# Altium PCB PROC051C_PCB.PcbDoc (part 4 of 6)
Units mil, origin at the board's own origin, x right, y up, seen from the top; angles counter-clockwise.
Board outline 3304.03 x 2647.77 mil, 6 copper layers (TOP, L2, L3, L4, L5, BOTTOM), stack 55.54 mil thick; 370 components, 273 nets, 1273 pads, 1381 vias.
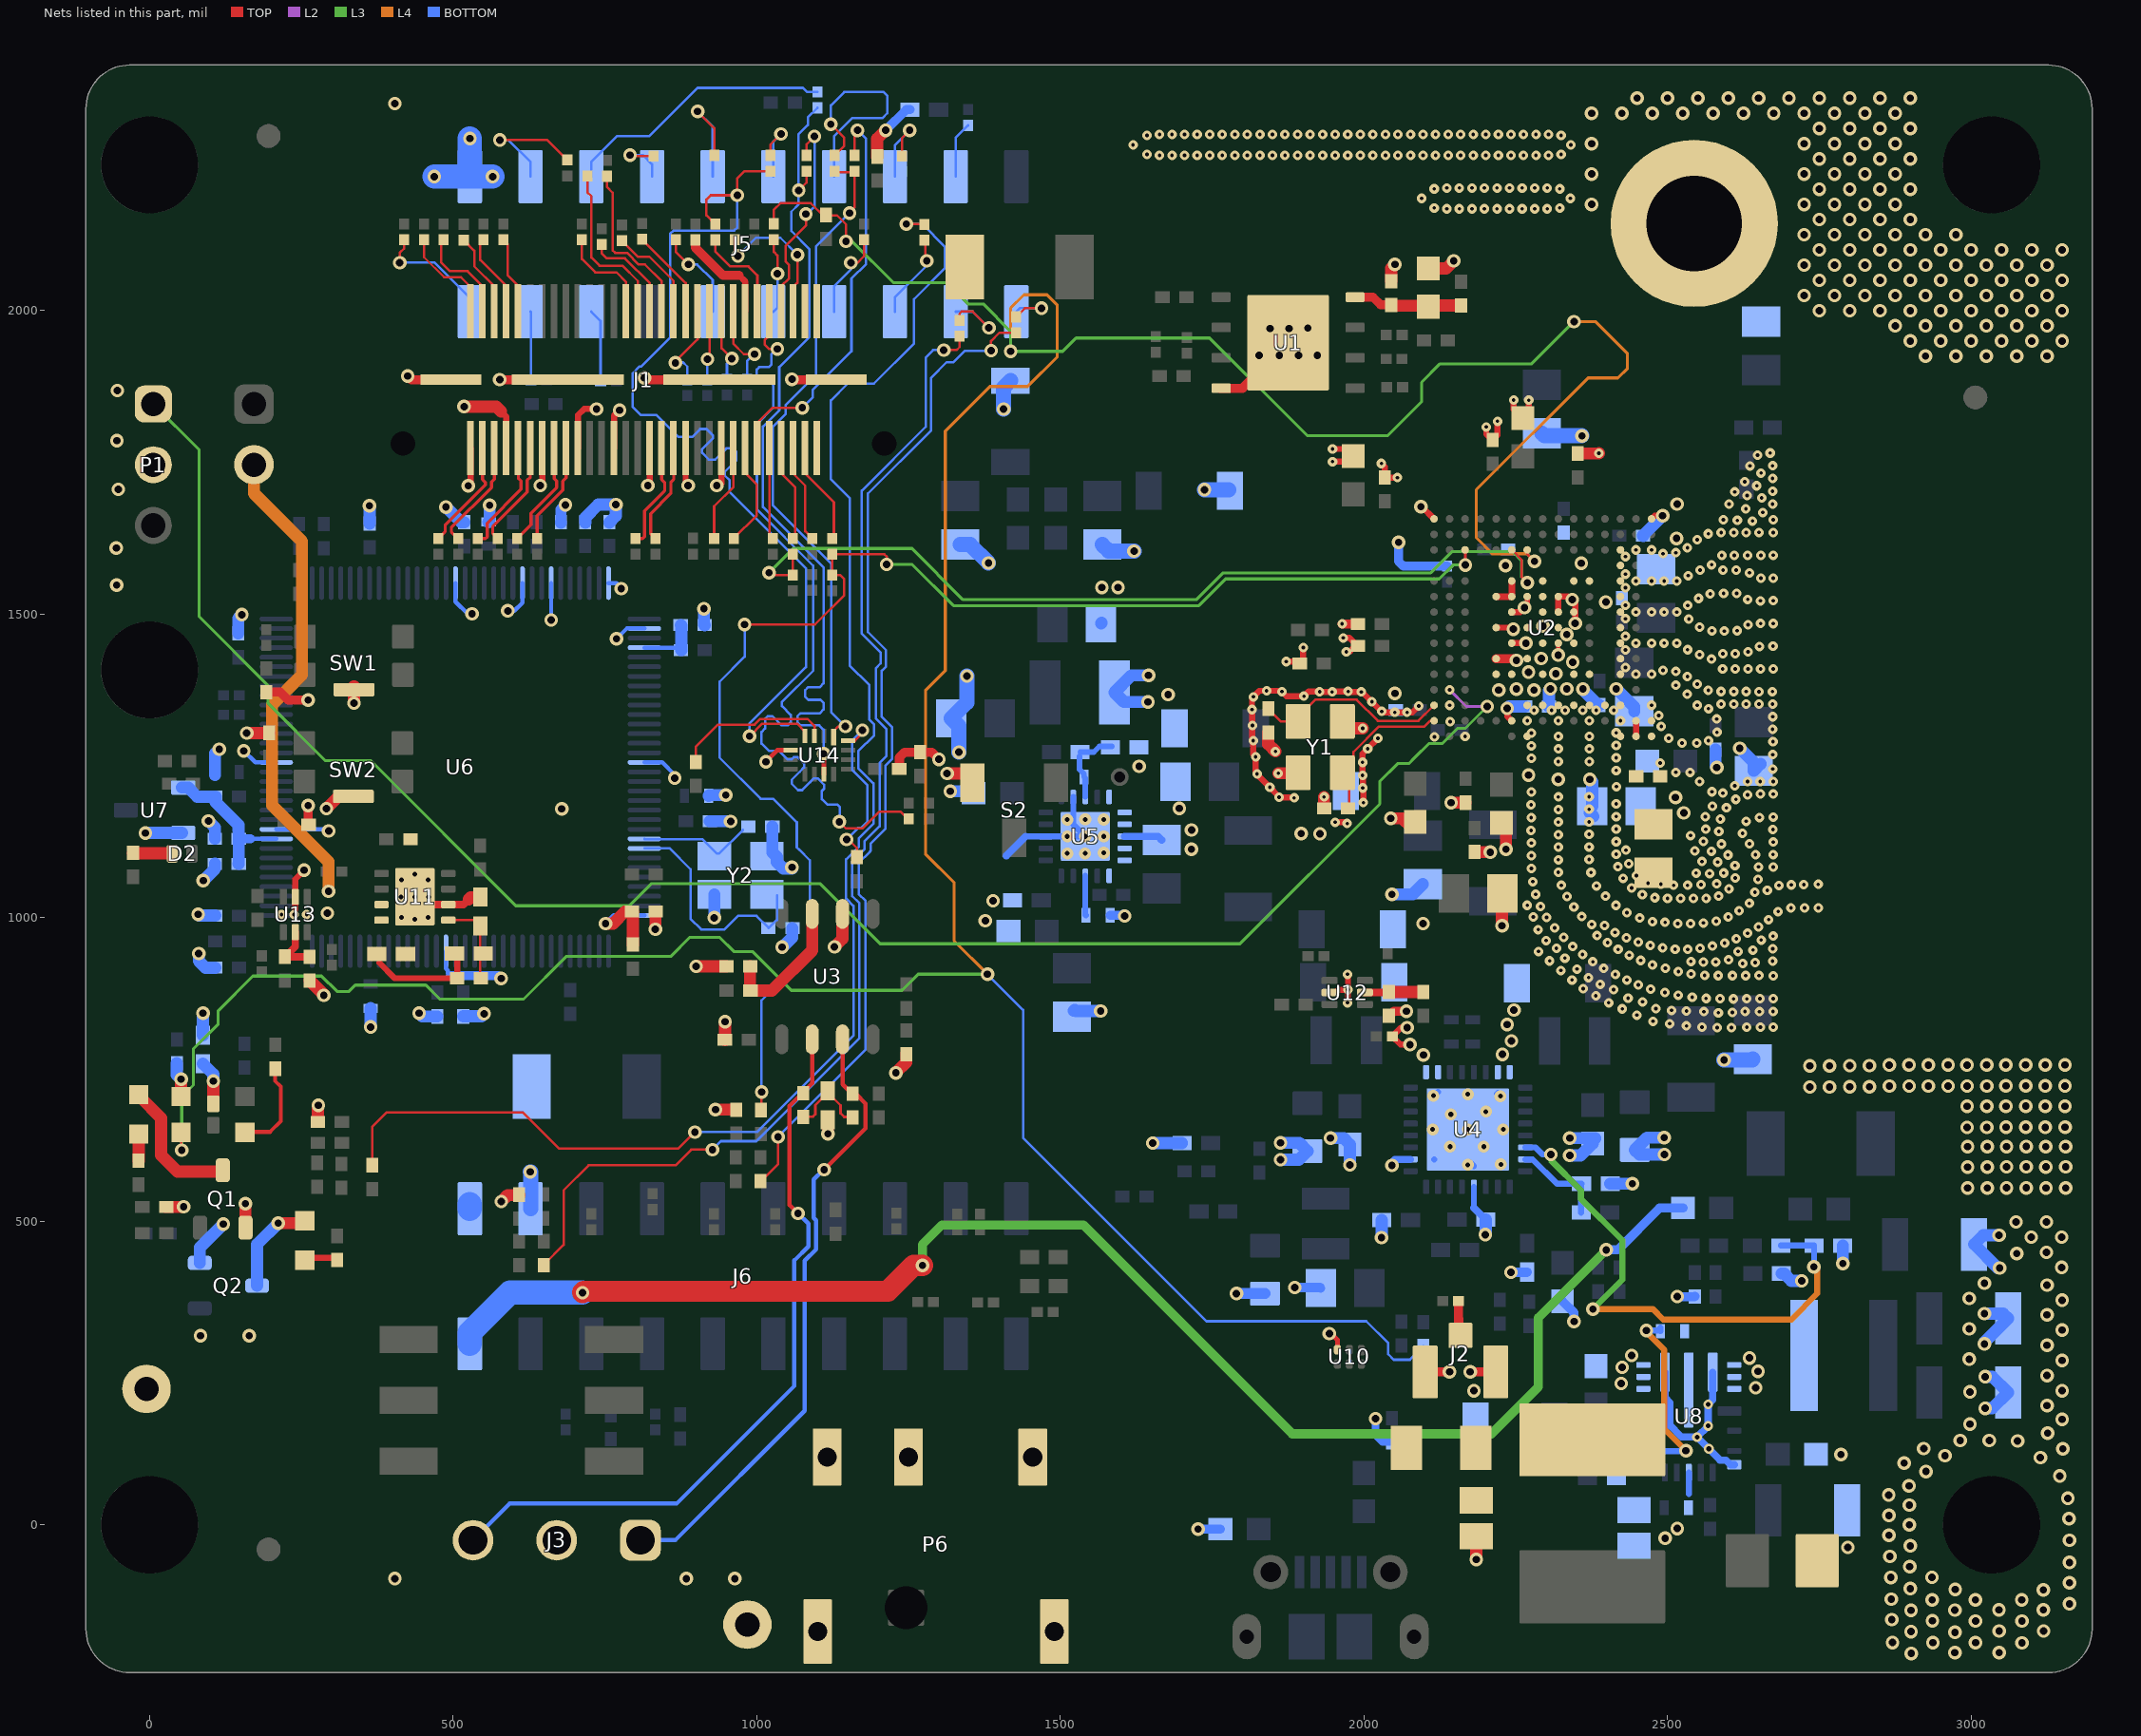
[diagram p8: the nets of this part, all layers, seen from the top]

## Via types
v1: diameter 22.4, hole 12.2, TOP to BOTTOM, tented both sides, 810 vias
v2: diameter 13.77/15.74 (per signal layer), hole 5.9, TOP to L2, tented both sides, 528 vias
v3: diameter 19.68, hole 7.87, TOP to BOTTOM, 23 vias
v4: diameter 19.68, hole 7.87, TOP to BOTTOM, tented both sides, 7 vias
v5: diameter 22.4, hole 12.1, TOP to BOTTOM, tented both sides, 7 vias
v6: diameter 16, hole 8, TOP to BOTTOM, tented both sides, 4 vias
v7: diameter 13.77/15.74 (per signal layer), hole 5.9, TOP to L2, tented top, 1 vias
v8: diameter 22.4/22.4/22.4/22.4/22.4/22.4 (per signal layer), hole 12.2, TOP to BOTTOM, tented both sides, 1 vias

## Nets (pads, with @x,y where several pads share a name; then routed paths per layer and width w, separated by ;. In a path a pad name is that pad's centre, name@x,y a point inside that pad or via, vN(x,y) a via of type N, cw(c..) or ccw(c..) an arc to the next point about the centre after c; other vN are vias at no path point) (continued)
AR_TDO_SOP0: R67.2 R71.1 R89.1 U2.N13 | length 2331.7
  TOP w4: v1(980,1483) 980.2,1482.8 1025.12,1482.8 1025.32,1483 1096,1483 1144,1531 1144,1558 1137.29,1564.71 R71.1@1124.33,1564.71 1124.25,1564.79 R67.2@1124.25,1598.73 1210.27,1598.73 1214,1595 v1(1214,1582) ; R89.1@1006.58,682.45 R89.1@1006.58,683.24 1008,684.66 v1(1008,713) ; U2.N13@2166.6,1605.85 2167,1606.25 2167,1605.85 v1(2167,1581)
  L3 w5: v1(1214,1582) 1256,1582 1324,1514 1728.14,1514 1772.14,1558 2124,1558 2147,1581 v1(2167,1581)
  BOTTOM w4: v1(980,1483) 980,1430 938.8,1388.8 938.8,1263.62 1006.42,1196 1027.14,1196 1066,1157.14 1066,1115.86 1069.66,1112.2 1070.09,1112.2 1087.5,1094.8 1087.5,943.5 1008,864 v1(1008,713)
AR_TMS: R65.2 R69.1 U2.N10 | length 1508.7
  TOP w4: v1(1020.36,1568.35) 1024,1564.71 R69.1@1059.25,1564.71 R65.2@1059.25,1598.73 ; U2.N10@2243.37,1605.85 2260,1589.22 2260,1561 v1(2269,1552)
  L3 w5: v1(1020.36,1568.35) 1060.11,1608.1 1255.7,1608.1 1339.8,1524 1724,1524 1768,1568 2110,1568 2145.3,1603.3 2244.56,1603.3 2259.7,1588.16 2259.7,1561.3 v1(2269,1552)
AR_VBGAP: C56.2 U2.B10 | length 54.1
  TOP w10: v1(2236,1345) 2236,1331.73 U2.B10@2243.37,1324.36
  BOTTOM w20: v1(2236,1345) 2239,1348 C56.2@2265.16,1348
AR_VOUT_PA: C10.2 C65.2 C83.2 R137.2 U2.A2 U2.B2 | length 25.6
  TOP w10: U2.A2@2448.09,1298.77 U2.B2@2448.09,1324.36
  other v1: 2526.79,1172.71 2513.12,1198
AR_VSENSE: P1.1 U2.D14 | length 3030.7
  L2 w5: v2(2141.01,1375.54) 2168.54,1348 v1(2203,1348)
  L3 w5: P1.1@6.27,1846.15 81.5,1770.92 81.5,1496 195.2,1382.3 195.2,1352.8 289,1259 364,1259 603.2,1019.8 790.3,1019.8 826.7,1056.2 1104,1056.2 1203.2,957 1795.63,957 2026.09,1187.46 2026.09,1224.71 2055.28,1253.9 2073.86,1253.9 2083.8,1263.84 2083.9,1263.84 2106.8,1286.74 2107.88,1286.74 2107.92,1286.78 2128.7,1286.78 2153.92,1312 2167,1312 v1(2203,1348)
AR_WARMRST: DS2.2 R15.1 R18.1 R149.2 U2.N9 | length 6596.4
  TOP w4: DS2.2@52,647.46 DS2.2@52,646.47 52,618 v1(53,617) ; R18.1@1028.21,2143.06 1028.21,2166.22 1038.99,2177 1089.07,2177 1111.26,2154.8 R15.1@1114,2157.53 1114,2156.75 1132.24,2156.75 1147,2141.99 v1(1147,2114) ; U2.N9@2268.96,1605.85 2268.96,1599.04 v1(2281,1587)
  L3 w5: v1(53,617) 53,705.23 72.16,724.39 72.16,784.16 113,825 113,847 170,904 283.26,904 308.65,878.61 328.4,878.61 338.79,889 455,889 478,866 616,866 686.22,936.22 858.1,936.22 889.58,967.7 938.89,967.7 962.29,944.3 992.7,944.3 1056.7,880.3 1239.3,880.3 1266,907 v1(1380,907) ; v1(1147,2114) 1157,2114 1225,2046 1313,2046 1348,2011 1373,2011 1418,1966 v1(1418,1933) 1504,1933 1526,1955 1745.9,1955 1906.9,1794 2039,1794 2095,1850 2095,1881.86 2125.44,1912.3 2276.3,1912.3 v1(2346,1982)
  L4 w5: v1(1380,907) 1325,962 1325,1058 1277.98,1105.02 1277.98,1374.51 1310.48,1407.01 1310.48,1801.63 1383.88,1875.03 1446.03,1875.03 1495,1924 1495,2009 1478,2026 1440,2026 1418,2004 v1(1418,1933) ; v1(2281,1587) 2268.3,1599.7 2211.3,1599.7 2185,1626 2185,1705 2369,1889 2418.26,1889 2434.06,1904.81 2434.06,1929.34 2381.7,1981.7 2346,1981.7 2341.7,1981.7 2342,1982 v1(2346,1982)
  BOTTOM w4: v1(1380,907) 1438.7,848.3 1438.7,637.3 1740.61,335.39 2003.85,335.39 2040,299.23 2040,281 2049,272 2075.69,272 R149.2@2098,294.31
AR_XTALM: C9.2 U2.C15 Y1.1 | length 326.1
  TOP w4: C9.2@1842.36,1344.03 1862.93,1323.46 1891.58,1323.46 1892.3,1323.46 1892.3,1331.6 1919.8,1359.1 1987.9,1359.1 2022.68,1324.32 2089.79,1324.32 U2.C15@2115.42,1349.95
AR_XTALP: C15.2 U2.B15 Y1.3 | length 258.4
  TOP w4: C15.2@1975.7,1180.4 1975.53,1180.57 1975.53,1228.43 1965.14,1238.82 1982.7,1256.38 1982.7,1273.22 2024.48,1315 2099.67,1315 2109.03,1324.36 U2.B15@2115.42,1324.36
CAN_RX: R12.1 U14.3 | length 260.6
  TOP w4: R12.1@900,1256.68 900,1282 936.05,1318.05 996.31,1318.05 1005.76,1327.5 1083.63,1327.5 1095.13,1316 U14.3@1095.13,1299.5
CAN_TX: R11.1 U14.16 | length 286.9
  TOP w4: v1(1148,1129) 1151,1129 1165,1115 R11.1@1165,1099.68 ; U14.16@1150.24,1291.62 1161.62,1291.62 1174,1304 v1(1174,1309)
  BOTTOM w4: v1(1148,1129) 1166.8,1147.8 1171.8,1147.8 1182.54,1158.54 1182.54,1218.04 1157,1243.58 1157,1292 v1(1174,1309)
CS1: R1.2 R17.1 U14.11 | length 1358.5
  TOP w4: v1(1069,2198) 1082,2211 R17.1@1082,2229.73
  TOP w8: v1(1110,1270) 1110.87,1269.13 U14.11@1110.87,1236.5
  BOTTOM w4: R1.2@1100,2334.01 1084.08,2318.08 1084.08,2305.8 1069,2290.72 v1(1069,2198) 1069,2175 1057,2163 1057,2131 1087,2101 1087,1957 1037,1907 1037,1835.7 1010.3,1809.01 1010.3,1676.7 1110,1577 1110,1386 1104,1380 1085,1380 1080,1375 1080,1364 1085,1359 1105,1359 1110,1354 1110,1343 1104,1337 1072,1337 1067,1332 1067,1322 1072,1317 1103,1317 1110,1310 v1(1110,1270)
D_LOGGER: J5.4 R60.1 | length 214.1
  TOP w4: v1(577,2281) 654.99,2281 R60.1@688,2247.99
  BOTTOM w4: v1(577,2281) 591,2281 627.5,2244.5 J5.4@627.5,2220.72
GND: C1.1 C2.1 C3.1 C4.1 C5.1 C6.1 C7.1 C8.2 C9.1 C10.1 C11.1 C12.1 C13.1 C14.1 C15.1 C16.1 C17.1 C19.2 C20.1 C21.2 C22.2 C23.2 C24.1 C25.2 C26.2 C27.2 C28.2 C29.2 C30.2 C31.2 C32.2 C33.1 C34.2 C35.2 C36.1 C37.2 C38.2 C39.1 C40.2 C41.2 C42.1 C43.1 C44.2 C45.1 C46.2 C47.1 C48.1 C49.1 C50.1 C51.1 C52.1 C53.1 C54.1 C55.2 C56.1 C57.1 C58.1 C59.2 C60.2 C61.2 C62.2 C63.2 C64.1 C65.1 C66.1 C67.1 C68.2 C69.1 C70.2 C71.1 C73.2 C74.1 C75.1 C76.2 C77.2 C78.2 C79.2 C80.2 C81.2 C82.2 C83.1 C84.1 C85.2 C86.1 C87.1 C89.1 C90.1 C91.1 C92.1 C93.2 C94.1 C95.2 C96.2 C97.1 C98.2 C99.2 C100.2 C101.2 C102.2 C103.2 C104.2 C105.2 J1.18 J1.24 J1.30 J1.36 J1.42 J1.48 J1.54 J1.60 J1.MP1 J1.MP2 J1.MP3 J1.MP4 J2.2 J2.3 J3.2 J5.2 J6.4 P1.2 P6.2 P6.3 P6.4 P6.5 pad.1 Q1.2 Q2.2 R13.1 R73.1 R79.1 R83.1 R86.2 R88.1 R96.1 R110.1 R114.1 R118.1 R123.2 R125.1 R126.2 R138.1 R139.1 R145.1 R147.2 R153.1 R158.2 R167.1 R174.1 R175.1 R190.1 R193.1 R208.2 S2.3 SW1.5 SW2.5 TP1.1 TP3.1 U1.4 U1.9 U2.A1 U2.A3 U2.A5 U2.A7 U2.A9 U2.A13 U2.A15 U2.B1 U2.B3 U2.B5 U2.B7 U2.B9 U2.B14 U2.C1 U2.C3 U2.C4 U2.C5 U2.C6 U2.C7 U2.C8 U2.C9 U2.C14 U2.E1 U2.E2 U2.E3 U2.E5 U2.E6 U2.E8 U2.E10 U2.E11 U2.F3 U2.F9 U2.F11 U2.G1 U2.G2 U2.G3 U2.G6 U2.G7 U2.G8 U2.G10 U2.H3 U2.H7 U2.H9 U2.H11 U2.J1 U2.J2 U2.J3 U2.J6 U2.J7 U2.J8 U2.J10 U2.K3 U2.K7 U2.K8 U2.K9 U2.K10 U2.K11 U2.L1 U2.L2 U2.L3 U2.L5 U2.L6 U2.L8 U2.L10 U2.M3 U2.N1 U2.N2 U2.N3 U2.R1 U2.R15 U3.2 U4.4 U4.10 U4.17 U4.18 U4.23 U4.24 U4.33 U5.2 U5.5 U5.6 U5.7 U5.8 U5.9 U5.10 U5.11 U5.18 U5.21 U6.10 U6.17 U6.48 U6.55 U6.58 U6.64 U6.66 U6.80 U6.114 U7.2 U8.3 U8.5 U8.6 U8.7 U8.8 U8.10 U8.11 U8.12 U8.13 U8.17 U8.20 U10.3 U11.6 U11.9@436.9,1034.5 U12.2 U13.2 U14.6 Y1.2 Y1.4 Y2.2 Y2.4 | length 9431.9
  TOP w7: U2.J7@2318.89,1503.49 U2.J7@2320.14,1503.49 U2.J7@2320.61,1503.49 ; v1@2320.14,1432.71 U2.G7@2320.14,1452.31
  TOP w7.5: v1(1015,1257) 1033.87,1275.87 U14.6@1055.76,1275.87
  TOP w8: v1(1943,315) 1943,318 1956.32,304.68 U10.3@1956.32,288.57
  TOP w9: v1@2268.96,1515.31 U2.K9@2268.96,1529.08
  TOP w10: v2@240,1013 240,1063.8 v1(254.6,1078.4) ; v1(524.98,1711.53) 528.62,1715.17 J1.60@528.62,1773.27 ; 579,1834 587.67,1825.33 J1.54@587.67,1773.27 ; v1(643.53,1711.97) 646.73,1715.17 J1.48@646.73,1773.27 ; J1.42@705.78,1773.27 705.78,1828 715.78,1838 v1(736,1838) ; J1.36@764.84,1773.27 764.84,1826.84 v1(774,1836) ; v1(820.61,1711.89) 823.89,1715.17 J1.30@823.89,1773.27 ; J1.24@882.95,1773.27 882.95,1716.05 v1(887,1712) ; v1(934,1712) 938.83,1712 942,1715.17 J1.18@942,1773.27 ; v2(1872,1422) 1895.7,1422 1900,1426.3 v2(1900,1445) ; v2(1885,1197.5) 1885,1198.4 v2(1860.1,1198.4) 1860.1,1199.9 v2(1845,1215) 1824,1236 v2(1824,1237) 1821.6,1239.4 v2(1821.6,1265) 1817.7,1268.9 v2(1817.7,1291.5) 1816.3,1292.9 v2(1816.3,1316.6) 1816.3,1342.3 v2(1815.7,1342.9) 1815.7,1361.7 v2(1818,1364) 1827.9,1373.9 v2(1839.7,1373.9) 1863.6,1373.9 v2(1865,1372.5) 1872.6,1364.9 v2(1901.3,1364.9) 1908.8,1372.4 v2(1927,1372.4) 1927.4,1372 v2(1947.6,1372) 1948.43,1372.83 v2(1974.02,1372.83) 1974.95,1371.9 1995.7,1371.9 v2(1995.8,1372) 1997,1372 2030.65,1338.35 v2(2050.83,1338.35) v2(2071,1338.35) 2079.79,1338.35 v2(2090.24,1348.8) ; U12.2@1943.37,876.9 1953.7,876.9 1958.3,881.5 v2(1973.69,881.5) ; v2(1948.3,1751.3) 1973,1751.3 C89.1@1982.1,1760.4 1970.4,1772.1 v2(1948.3,1772.1) ; v2(1952.62,1157.3) 1970.3,1157.3 v2(1972.4,1155.2) ; v2(1966,1461) 1976,1461 1989.66,1447.34 1986.31,1444 1982,1444 1976,1438 v2(1971,1438) ; v2(1973,859.98) 1973.69,860.66 v2(1973.69,881.5) ; v2(1973,907) 1973.69,906.31 v2(1973.69,881.5) ; v2(1999.1,1189.7) 1999.1,1212.8 v2(1998.1,1213.8) 1998.1,1234 v2(1997.7,1234.4) v2(1997.7,1256.1) 1997.7,1270 v2(2006.2,1278.5) v2(2023.15,1295.45) ; v2(2028.8,1748.3) 2034.5,1742.6 C6.1@2034.5,1725.28 2034.5,1724.9 v2(2055.3,1724.9) ; v1(2071,819) 2060.99,819 R167.1@2046.59,804.6 2060.19,791 v1(2076,791) ; v1(2094,1677) 2095.45,1677 U2.R15@2115.42,1657.03 ; v2(2201.4,1808.4) 2201.4,1796.9 2211.4,1786.9 2211.95,1786.9 2219.9,1794.85 v2(2219.9,1817.8) ; U2.H11@2217.78,1477.9 2248.55,1477.9 v1(2246,1475.35) v1@2246,1472 ; U2.G10@2243.37,1452.31 v1@2266.94,1452.31 ; U2.J10@2243.37,1503.49 2257.14,1503.49 v1(2264.45,1510.8) ; v2(2246.6,1852.7) 2246.6,1837.55 2261.25,1822.9 C87.1@2261.8,1822.9 2271.5,1832.6 v2(2271.5,1852.5) ; U2.J7@2320.14,1503.49 U2.K7@2320.14,1529.08 2336.12,1529.08 2348,1517.2 v1(2348,1485) ; U2.R1@2473.68,1657.03 2478.69,1662.04 v1(2491.96,1662.04)
  TOP w11: U2.K11@2217.78,1529.08 U2.K10@2243.37,1529.08 U2.L10@2243.37,1554.67
  TOP w12: v4(436.9,1034.5) 449.7,1021.7 516.9,1021.7 525.7,1030.5
  TOP w15: R73.1@192.05,1372.02 214.98,1372.02 228.5,1358.5 v1(261,1358.5) ; R79.1@261.15,1153.14 v1(261.15,1185) ; v1(425.2,1892.3) 431.24,1886.26 J1.MP4@496.12,1886.26 J1.MP4@496.73,1886.26 ; v1(576.76,1886.26) J1.MP3@688.64,1886.26 J1.MP3@689.25,1886.26 ; v1(815,1889) 817.74,1886.26 J1.MP2@938.64,1886.26 J1.MP2@939.25,1886.26 ; v1(1058,1887) 1058.74,1886.26 J1.MP1@1131.16,1886.26 J1.MP1@1131.77,1886.26 ; C97.1@1234.68,1245 1235,1245.32 1235,1264 1243.69,1272.69 R208.2@1269,1272.69 1288.31,1272.69 v1(1300,1261) ; U1.4@1762.93,1872.18 U1.4@1764.89,1872.18 1800.13,1872.18 U1.9@1875.13,1947.18 ; v2(1964,1484) C4.1@1990.32,1484 ; C91.1@2041,838.32 2041.32,838 2049.32,846 v1(2070,846) ; J2.2@2100.93,252 v1(2141,252) ; v1(2175,252) J2.3@2217.07,252 ; U2.F11@2217.78,1426.72 2248.28,1426.72 v1(2251,1424)
  TOP w20: R110.1@26.62,523.77 R110.1@27.4,523.77 v1@55,523.77 ; Q1.2@157.98,489.51 v1(158,529) ; v1(160,1304.2) C11.1@197.3,1304.2 ; C92.1@263.6,896.9 287.1,873.4 v1(287.1,872.3) ; R114.1@277.32,664 277.32,690.32 v1(278,691) ; v1(291.2,1179.7) 311.4,1199.9 SW2.5@335.7,1199.9 ; v1(336.65,1353.5) SW1.5@336.65,1375.52 SW1.5@336.65,1381.42 ; v1(518,1842) 571,1842 579,1834 ; 525.7,1030.5 529.11,1033.91 R193.1@544.9,1033.91 ; v1(579.2,532.5) 589.85,543.15 R96.1@608.78,543.15 ; v1(833,981) 833.3,981.3 C71.1@833.3,1010.5 ; v1(900,920) C16.1@949.91,920 C16.1@950.3,920 ; v1(932,684) 964.87,684 R88.1@966.12,682.75 ; C20.1@947.89,798.85 v1(947.89,828.89) ; v1(1117.1,644.1) C24.1@1117.1,667.48 C24.1@1117.1,671.8 ; v1(1128,952) 1141.31,965.31 U3.2@1141.31,1006.33 U3.2@1141.31,1007.31 ; R13.1@1198.4,2252.95 R13.1@1198.4,2253.73 1198.4,2283 v1(1212.4,2297) ; v1(1229,744.5) 1246.3,761.8 R86.2@1246.3,775.01 R86.2@1246.3,775.8 ; v1(1313.43,1237.76) 1339.62,1237.76 S2.3@1355.1,1222.28 ; C9.1@1842.36,1305.43 C9.1@1842.36,1305.05 1842.36,1285.94 v2(1854.3,1274) ; v2(1859,1238) 1891.48,1238 Y1.2@1892.3,1238.82 ; C15.1@1934.32,1180.4 v2(1934.32,1198.99) ; Y1.4@1965.14,1323.46 1976.6,1312 v2(1998,1312) ; v1(2044.25,1163.62) 2063.4,1163.62 2076.78,1150.23 C14.1@2084.45,1157.9 ; C2.1@2044.9,2048.2 C2.1@2044.9,2048.59 2044.9,2069.9 v1(2051,2076) ; C1.1@2102,2068.5 C1.1@2104.5,2071 ; C1.1@2106,2069.5 2135.5,2069.5 v1(2148,2082) ; v1(2143.51,1189.51) C12.1@2167.2,1189.51 C12.1@2167.2,1189.9 ; C90.1@2184,1108.32 2207.68,1108.32 v1(2208,1108) ; v1(2185,-57) C79.2@2185,-18.53 C79.2@2187.47,-21 ; C17.1@2213.1,1028.1 C17.1@2213.1,1037.6 ; C13.1@2226.5,1156.4 2234,1148.9 v1(2234,1113) ; v1(2227.44,987) 2227.44,1039.44 C17.1@2228,1040 ; C3.1@2352,1764.68 2386.68,1764.68 v2(2387,1765)
  BOTTOM w7: v1(155,1275) 174.09,1255.91 U6.17@208.64,1255.91 ; U6.10@208.64,1145.68 292.32,1145.68 v1(295,1143) ; U6.114@488.17,944.89 488.17,916.23 491.4,913 491.5,913 491.5,908.5 495.2,904.8 ; U6.48@503.92,1551.19 503.92,1520.59 524.01,1500.5 v1(531,1500.5) ; v1(590,1505.5) 601,1505.5 614.15,1518.65 U6.55@614.15,1551.19 ; v1(661.4,1490.3) U6.58@661.4,1551.19 ; U6.64@755.88,1551.19 769,1551.19 777,1543.19 v1(777,1542) ; v1(769,1459.5) 785.89,1476.39 U6.66@814.94,1476.39 ; U6.80@814.94,1255.91 844.49,1255.91 865,1235.4 v1(865,1230)
  BOTTOM w10: C61.2@106.73,1233.92 106.53,1233.72 106.53,1233.62 106.73,1233.62 106.94,1233.42 108.35,1234.83 108.35,1235 C61.2@107.94,1235.41 ; 1443.04,1134.04 U5.18@1476.04,1134.04 ; U5.18@1476.08,1134 v3(1511.46,1134) v4(1541.04,1134) 1521.35,1153.69 U5.2@1521.35,1198.96 ; U4.33@2115.94,602.06 U4.33@2116,602 ; U4.33@2121,712 U4.33@2122.06,713.06 ; U4.33@2175,597 U4.33@2181.11,590.89 ; 2181.11,521.89 U4.4@2181.11,556.78 ; U4.33@2219,710 U4.33@2220.48,711.48 ; 2535,51 U8.20@2535,86.19
  BOTTOM w12: 1411,1102 1443.04,1134.04 ; U5.8@1606,1134 1661,1134 C59.2@1667,1128 ; v1(2019,175) 2019,148 2030.68,136.32 R174.1@2046,136.32 ; v1(2046,592) 2046,597 2051.06,602.06 U4.10@2076.78,602.06 ; 2181.11,521.89 2200,503 C22.2@2200.62,503 ; U8.3@2460.2,155.09 2493.09,155.09 2503.01,165.01 2523.01,145 v6@2548.23,145 ; U8.8@2495.63,251.54 2495.63,209.5 2504,201.13 2504,166 ; U8.10@2574.37,251.54 2574.37,206 v6(2567,198.63) v6(2567,163) v6(2548.62,144.62) v6(2568,125.23) 2586.53,106.7 2596.3,106.7 2604.02,98.98 U8.17@2609.8,98.98
  BOTTOM w15: 495.2,904.8 574.3,904.8 v1(579.1,900) ; v1(1212.4,2297) 1246.4,2331 R147.2@1252.38,2331 ; C73.2@1582,1004 v1@1605,1004 ; v1(1727,-7) R175.1@1763.5,-7 ; v1(1886,391) 1928,391 C93.2@1929,390 ; v1(2057.1,1618.38) 2057.1,1586.9 2065.01,1578.99 C8.2@2137,1578.99 ; v1(2242,416) 2267.38,416 2268,415.38 R158.2@2269,416.38 ; C94.1@2327,368.5 2346,349.5 v1(2346,335) ; v1@2516.32,376.32 v1(2516,376) 2544.68,376 R138.1@2545,376.32
  BOTTOM w18: R125.1@677.52,1651.53 677.52,1672.52 v1(685,1680) ; v1(1790,381) C81.2@1837,381
  BOTTOM w20: v1(-7,1139.5) -2,1139.5 -2,1139.69 U7.2@53.36,1139.69 ; v1(80,1005.5) 81.94,1003.56 C69.1@107.96,1003.56 C69.1@108.35,1003.56 ; v1(81,941) 81,929 92.26,917.74 R153.1@107.96,917.74 ; Q2.2@82.76,431.4 82.76,456.76 v1(121.4,495.4) ; R118.1@88,806.62 v1(88,843) ; v1(88.4,1061.1) 107.95,1080.65 C67.1@107.95,1088.8 ; v1(97,1159.5) 107.89,1148.61 C66.1@107.89,1130.1 ; C61.2@107.94,1235.41 107.94,1270.74 v1(114.7,1277.5) ; C50.1@145.95,1468 C50.1@145.95,1468.39 145.95,1493.15 v1(152,1499.2) ; v1(362,1678.5) 362.52,1677.98 C43.1@362.52,1649.53 C43.1@362.52,1649.15 ; v1(364,820) C76.2@364,851 ; v1(444,843) 449.54,837.47 C75.1@473.68,837.47 ; v1(488,1676.5) 513.35,1651.15 C42.1@518.22,1651.15 ; C74.1@516.6,837.85 546.85,837.85 v1(550.9,841.9) ; C41.2@558.3,1651.85 560,1653.55 v1(560,1679.5) ; R125.1@677.52,1650.75 R125.1@677.52,1651.53 ; R126.2@717.68,1651.05 R126.2@717.68,1651.84 717.68,1659.18 739,1680.5 v1(768,1680.5) 768,1661.77 R123.2@757.28,1651.05 ; v1(913,1509) 913,1482.93 C49.1@914.04,1481.9 ; C62.2@921,1201 922,1202 v1(949,1202) ; C64.1@922.68,1159 955.5,1159 956,1158.5 v1(957,1158.5) ; v1(930,1000) 930.15,1000.15 Y2.4@930.15,1038.54 ; C63.2@1025.69,1150 1025.68,1107.86 1033.27,1100.28 1033.27,1091.73 1043.67,1081.33 1058,1081.33 v1(1058,1083) ; v1(1041.8,951.5) 1041.8,950.8 1058.68,967.68 C70.2@1058.69,983 ; v1(1318.83,1208.21) 1354.4,1208.21 R83.1@1357.35,1205.26 ; C40.2@1522.19,846.92 1523.74,848.47 1525.9,846.31 v1(1566.29,846.31) ; C95.2@1567.13,1485 C95.2@1568,1485.87 ; v1@1605,1004 v1(1606,1003) ; v1(1644.42,1355.5) 1604.71,1355.5 C44.2@1589.09,1371.13 1617.13,1399.18 v1(1645.22,1399.18) ; v1(1652,629) R190.1@1700.38,629 ; C19.2@1777.56,1705 C19.2@1779.27,1703.29 ; v1(1862.59,601.49) 1892.86,601.49 C35.2@1907,615.63 1893.52,629.11 v1(1862.59,629.11) ; v1(1945,637) 1966.5,637 C36.1@1977,626.5 v1(1977,593) ; v1(2029,473) 2029.38,473.38 C82.2@2029.38,502 ; v1(2046,1038.54) 2080.21,1038.54 C104.2@2097.09,1055.42 ; v1(2200,478) 2200.62,478.62 C22.2@2200.62,503 ; C56.1@2304.53,1348 2304.53,1374.53 v1(2307,1377) ; v1(2339,608.45) 2356.81,608.45 C54.1@2376.63,628.27 ; v1(2339,637) 2380.5,637 C54.1@2381,636.5 ; v1(2360.75,1376.8) 2360.75,1375.55 2385.82,1350.47 C51.1@2387.91,1350.47 ; C65.1@2372,1173 C65.1@2378,1167 ; v1(2372,1228) 2376,1224 C65.1@2376,1183.57 ; C77.2@2405.62,562 v1(2442,562) ; v1(2415.62,1376.86) 2445.08,1347.41 C52.1@2445.08,1340.29 ; C39.1@2460,1628.68 C39.1@2459.68,1629 2459.68,1629.68 v1(2491.96,1662.04) v1(2491.96,1662.04) ; v1(2494.45,638) 2466.44,638 C46.2@2446.07,617.63 2453.7,610 v1(2494.97,610) ; C57.1@2579,1277 2579,1249.66 v1(2581.16,1247.5) ; v1(2619,1279) 2642,1256 C58.1@2642,1242 C58.1@2653.2,1253.2 ; R139.1@2687.62,414 2692,414 2704,402 v1(2721,402) ; v1(2788.62,430.38) C78.2@2788.62,460 ; v1(3022,298) 3022,301.04 C30.2@3060.96,340 3052.96,348 v1(3022,348) ; v1(3023,192) 3034.96,192 C29.2@3060.96,218 3034.96,244 v1(3023,244) ; v1(3046,477) 3019.96,477 C31.2@3004.96,462 3043.96,423 v1(3047,423)
  BOTTOM w25: v1(627,581.5) 627.5,581.5 J6.4@627.5,520.72 ; v1(1333,1272.69) 1333,1315.69 C96.2@1320.21,1328.48 1346.04,1354.31 v1(1346.04,1398) ; C103.2@1335.31,1614.61 1351.47,1614.61 v1(1381.63,1584.45) ; v1(1406.57,1838) 1406.57,1873.41 C37.2@1417.79,1884.62 ; C98.2@1569,1614.51 1579.53,1603.98 v1(1621.43,1603.98) ; v1(1737.53,1705) C19.2@1777.56,1705 ; C100.2@2293,1798 2297.3,1793.7 v1(2358.99,1793.7) ; v1(2592.98,765.92) 2639.3,765.92 C80.2@2640.38,767
  BOTTOM w40: v1(469,2220.72) J5.2@527.5,2220.72 ; v1(527.5,2283.5) J5.2@527.5,2220.72 ; v1(565,2220.72) J5.2@527.5,2220.72
  other v1: 2901.31,-211.79 2973.18,-210.54 3046.16,-210.54 2870.41,-193.77 2937.07,-194.14 3007.25,-194.14 3083.71,-194.24 2973.55,-177 2901.17,-175.74 3046.16,-174.68 3119.29,-174.68 2936.3,-157.9 3007.25,-158.28 3083.71,-158.39 2869.37,-155.97 2901.17,-140.65 2973.18,-140.5 3045.91,-139.97 3118.84,-139.97 3162,-130.02 2935.92,-123.56 3007,-123.56 3083.46,-123.67 2868.72,-122.32 3119.08,-107.06 2973.78,-106.37 2900,-105 3161.85,-95.39 404,-88.5 884,-88.5 964,-88.5 2867.68,-86.6 2935.56,-86.48 2898.88,-68.71 3162,-61.96 2866.11,-51.88 2796.87,-37 2900,-34.53 3162,-25.28 2496,-22 2864.72,-17.26 2516,-6 2898.33,0 3161.35,10.21 2864.72,15.51 2898.33,32.58 3159.31,43.72 2864.26,49.21 2897.74,64.31 3146,80.47 2925.65,87.98 2889.65,101.83 3114.04,110.95 2957,114 2785.6,115.82 3151.17,125.15 2921.96,125.83 3076.52,138.19 2982,139 3030,139 3126.05,151.01 2998,166 3150,173.81 3125,196.64 2998,219 2181.22,221 3150,221 2645,226 2423.67,232.91 3125,246 2649,253 2425.13,259.59 3150,271 2997,273 2635,275 2441,279 3125,296 84,311.5 164,311.5 3150,321 2997,323 3125,346 3150,370 2997,373 3125,395 3022,398 3149,424 3075,447 3124,449 3099,474 3149,474 3074,499 3124,499 56,524 2994.26,554.8 3026.78,554.86 3058.36,555.07 3090.89,555.13 3123.16,554.94 3155.68,555 2994.18,589.42 3026.7,589.48 3058.28,589.69 3090.81,589.75 3123.08,589.56 3155.6,589.62 2994.13,622.85 3026.66,622.91 3058.23,623.12 3090.76,623.18 3123.03,622.99 3155.55,623.05 2993.36,654.72 3025.88,654.78 3057.46,655 3089.99,655.05 3122.26,654.86 3154.78,654.92 2993.28,689.35 3025.8,689.41 3122.17,689.49 3057.38,689.62 3089.9,689.68 3154.7,689.55 2734.34,721.25 2766.87,721.31 2800.11,721.69 2832.63,721.74 2865.3,722.77 2897.82,722.83 2929.52,722.77 2962.04,722.83 2993.23,722.77 3025.76,722.83 3057.33,723.04 3089.86,723.1 3122.13,722.91 3154.65,722.97 2734.26,755.88 2766.79,755.94 2800.02,756.31 2832.55,756.37 2865.21,757.4 2897.74,757.45 2929.44,757.4 2961.96,757.45 2993.15,757.4 3025.67,757.45 3057.25,757.67 3089.78,757.73 3122.05,757.54 3154.57,757.6 2098,774 2228,775 2243,797 2236,824 2247,848 2097.46,990.5 1376.48,995.16 1389.27,1027.91 1716,1113 1927.6,1138.34 1896.53,1138.8 1716.13,1144.48 678.8,1179.5 1696,1180 2320,1228 1629.78,1249.49 1677.49,1367.63 2051,1369.53 2222,1375 2280,1375 2251,1376.8 2334,1377 2316,1402 2271.2,1404.5 2344,1421 2292,1427 2320.15,1432.7 2266.95,1452.3 2334,1466.51 2295.05,1480.4 2398.5,1519.98 2343,1524 1568.39,1544.14 1594.84,1544.14 -54.3,1547.9 2233,1580 2358,1584 -54.8,1609.1 2514.69,1624.81 2515.86,1681.5 -51.5,1705.6 -53.7,1785.9 -52.9,1868.3 2925,1925 2975,1925 3025,1925 3075,1925 3125,1925 2900,1950 2950,1950 3000,1950 3050,1950 3100,1950 3150,1950 2875,1975 2925,1975 2975,1975 3025,1975 3075,1975 3125,1975 2750,2000 2800,2000 2850,2000 2900,2000 2950,2000 3000,2000 3050,2000 3100,2000 3150,2000 2725,2025 2775,2025 2825,2025 2875,2025 2925,2025 2975,2025 3025,2025 3075,2025 3125,2025 2750,2050 2800,2050 2850,2050 2900,2050 2950,2050 3000,2050 3050,2050 3100,2050 3150,2050 2725,2075 2775,2075 2825,2075 2875,2075 2925,2075 2975,2075 3025,2075 3075,2075 3125,2075 2750,2100 2800,2100 2850,2100 2900,2100 2950,2100 3000,2100 3050,2100 3100,2100 3150,2100 2725,2125 2775,2125 2825,2125 2875,2125 2925,2125 2975,2125 2750,2150 2800,2150 2850,2150 2900,2150 2375,2175 2725,2175 2775,2175 2825,2175 2875,2175 2750,2200 2800,2200 2850,2200 2900,2200 2375,2225 2725,2225 2775,2225 2825,2225 2875,2225 2750,2250 2800,2250 2850,2250 2900,2250 2375,2275 2725,2275 2775,2275 2825,2275 2875,2275 2750,2300 2800,2300 2850,2300 2900,2300 2375,2325 2425,2325 2475,2325 2525,2325 2575,2325 2625,2325 2675,2325 2725,2325 2775,2325 2825,2325 2875,2325 404,2341 2450,2350 2500,2350 2550,2350 2600,2350 2650,2350 2700,2350 2750,2350 2800,2350 2850,2350 2900,2350
  other v2: 2581.79,819 2605.35,819 2556.6,820 2630.55,820 2653,820 2674.2,820 2531.2,821.87 2503.31,825.5 2476.25,829.44 2449.63,839.67 2583.7,843.5 2607,843.9 2560,845.4 2651.5,845.4 2531.2,846.2 2627.6,845.6 2673.8,845.6 2506.5,847.4 2425.52,849.9 2481,850.5 2403.07,859.98 2459,861.5 2608.6,866.4 2630.6,866.5 2563.5,867.1 2586.4,866.6 2652.2,866.6 2674.1,866.9 2435,867.5 2540.7,869 2381.92,871.42 2517.6,872.5 2495.5,876.9 2411,881.5 2472,882.5 2361.23,883 2389,890.5 2452,889.5 2342.66,897.5 2433,897.5 2370,901.5 2673.9,904.5 2561.2,905.1 2583.6,904.7 2607.1,904.7 2628.8,904.7 2650.8,904.8 2414,906.5 2538.7,907.4 2517.9,911.5 2324.3,913.17 2351,915.5 2395,916.5 2496.6,916.7 2475.1,922.5 2623.8,924.7 2644.4,926.2 2559,926.8 2579.6,927.3 2377,927.5 2538.4,928 2673,928.5 2305.8,929 2455.7,929.7 2600.4,930.7 2331,933.5 2436.9,938.3 2360,939.5 2616,944.5 2640.7,946.8 2418.6,947.8 2512.5,948.1 2533.1,947.9 2673.5,949.1 2317,949.5 2492,950.5 2553.7,949.6 2344,952.5 2574,953.3 2471.7,954.3 2594,958.3 2401.3,959.1 2451.8,959.9 2300,962.5 2654.2,963.3 2613.3,965.5 2432.4,967.1 2329,967.5 2384.1,970.5 2673.8,969.7 2631.9,974.5 2413.7,975.8 2287,980.5 2314,983.5 2649.7,984.9 2396.4,987.1 2375.1,989.1 2517,990.5 2538,990.5 2496,992.5 2559,991.5 2475,993.5 2580,994.5 2666.5,996.9 2301,1000.5 2454,999.5 2279,1001.5 2358.8,1001.8 2600,1001.5 217.33,1005.44 238,1005.44 258.67,1005.44 2433,1008.5 2682.2,1010.3 2618,1011.5 2703.3,1016.4 2725.8,1016.4 2748.6,1016.3 2291,1018.5 2345.8,1017.8 2269,1020.5 2415,1020.5 2634.7,1023.7 2500,1032 2521.5,1032 2542.5,1032 2563.5,1032 2479,1033 2334.5,1035.1 2398,1035.5 2584,1035.5 2283,1038.5 2458.5,1038 2643.9,1042.2 2664.3,1045.3 2601,1047.5 2441,1049 2383,1052.5 2683.3,1053.3 2325,1053.5 2510,1053.5 2533,1053.5 2555,1054.5 2703.9,1054.2 2724.5,1054.5 2748.1,1055 2489,1055.5 2580.9,1055.9 2468,1057 2278,1059.5 2649,1063.2 2427,1065 2611.5,1065.5 2448.53,1069.43 2569.1,1072.9 2374,1074.5 2547,1073.6 2592.5,1073.7 2320.1,1074.8 2275.6,1081.3 2673.9,1083.4 2418,1084 2649.8,1083.8 2611.1,1086.1 2436.04,1089.06 2582.4,1091.7 2556.9,1092.6 2320.1,1095.5 2370.9,1095.9 2275.7,1102.1 2415.5,1104.5 2599.5,1103.5 2644.9,1103.9 2673.8,1104.1 2545,1110 2572.1,1109.6 2431.71,1111.35 2320.1,1116.2 2370.9,1116.6 2589,1121.5 2634.9,1121.9 2275.6,1123.1 2415.5,1125.35 2674,1124.7 2559.1,1125.6 2538,1135.5 2320.1,1136.9 2370.9,1137.3 2623.5,1139.1 2584.5,1142 2275.3,1143.7 2673.6,1145.3 2415.5,1146.05 2563,1145.9 2320.1,1157.6 2370.9,1158 2629.3,1158.9 2587,1162.5 2275.5,1165 2651.2,1165.2 2562,1166.5 2674,1165.9 2415.5,1166.75 2320.1,1178.3 2370.9,1178.7 2597,1181 2574,1183.5 2275.3,1185.9 2415.5,1187.4 2612.5,1195 2320.1,1199 2370.9,1199.4 2632,1202.5 2653,1204 2674.1,1203.8 2591.09,1205.35 2275.7,1207 2573,1207.5 2415.7,1216.1 2610.7,1217.31 2553,1224.5 2652.6,1224.4 2674.1,1224.4 2631.9,1224.5 2513.5,1239.5 2537,1239.5 2415.45,1242.6 2673.5,1245 2487.68,1255.06 2320.14,1257.37 2371.32,1257.37 2275.85,1262.7 2415.45,1263.3 2673.5,1268.7 2320.14,1278.07 2371.32,1278.07 2275.85,1283.35 2415.45,1283.95 2523.97,1287.74 2548.18,1287.74 2673.7,1290 2567.38,1291.5 2502.01,1295.45 2116,1298 2166.6,1298.5 2320.14,1298.77 2371.32,1298.77 2275.85,1304 2415.45,1304.6 2581.51,1305.43 2673,1310.6 2489.64,1315 2142,1323 2268.96,1324.36 2320.14,1324.36 2371.32,1324.36 2422.5,1324.36 2581.15,1327.44 2673.2,1331.2 2485.68,1333.14 2029.24,1339.96 2280.15,1341.9 2309.05,1341.9 2331.35,1341.9 2360.25,1341.9 2382.55,1341.9 2411.45,1341.9 2567.38,1344.42 2141.01,1349.95 2473.68,1349.95 2548.69,1350 2588.3,1351.99 2609,1351.8 2629.7,1351.8 2650.8,1351.8 2673,1351.8 2013.17,1356.03 2532.56,1368.04 2650.7,1372.28 2672.8,1372.48 2588.3,1372.68 2609,1372.68 2629.7,1372.68 2567.2,1374.48 2513.5,1383 2549,1384.8 2532.7,1397.48 2448.09,1401.13 2473.68,1401.13 2513.5,1405.68 2492.4,1407.28 2590.8,1410 2611.7,1409.9 2632.5,1409.9 2653.2,1410 2674.1,1409.9 2430.65,1412.3 2572.4,1426 2553,1433.5 2591.1,1434.8 2611.7,1434.8 2632.6,1437.9 2430.65,1441.3 2533,1441.5 2651.5,1446.9 2673.7,1447.3 2448.09,1452.31 2473.68,1452.31 2494.38,1452.31 2515.08,1452.31 2430.65,1463.5 2593.7,1472.2 2573,1472.7 2614.5,1472.8 2552.8,1478.9 2632.8,1482.4 2653.3,1484.7 2674.1,1484.6 2430.65,1492.5 2535.1,1492.1 2448.09,1503.49 2473.68,1503.49 2494.38,1503.49 2515.08,1503.49 2533.2,1514.4 2430.65,1514.7 2652.9,1522 2673.9,1522.2 2632.1,1524.3 2550.9,1526 2570.3,1533.6 2592.3,1534.3 2613.8,1534.1 2430.65,1543.7 2448.09,1554.67 2473.68,1554.67 2494.38,1554.67 2515.08,1554.67 2653.6,1559.4 2674.2,1559.4 2534,1563.5 2430.65,1565.9 2634.9,1568.2 2613.2,1572.5 2553.5,1572.6 2591.4,1572.6 2572.6,1581.5 2430.65,1594.9 2589.3,1596.8 2609.9,1596.8 2631.8,1596.7 2653.6,1596.8 2674.2,1597.1 2492.4,1599.7 2513.5,1601.3 2448.09,1605.85 2473.68,1605.85 2532.7,1609.5 2549,1622.5 2567.2,1632.5 2588.3,1634.3 2609,1634.3 2629.7,1634.3 2674,1634.5 2650.7,1634.7 2615,1654.5 2640,1653.5 2592,1655.5 2674,1655.5 2657,1667.5 2629,1673.5 2601.2,1681.5 2673,1681.5 2655,1691.5 2631,1695.5 2610.7,1701.5 2673,1702.5 2647,1711.5 2627,1718.2 2673,1723.5 2654,1732.5 2635.9,1744.2 2673,1744.5 2648.4,1761.9 2669,1765.5 2136.47,2167.74 2157.14,2167.74 2177.81,2167.74 2198.48,2167.74 2219.15,2167.74 2239.82,2167.74 2260.49,2167.74 2281.16,2167.74 2301.83,2167.74 2115.8,2169.2 2322.5,2169.2 2095.07,2184.9 2339.8,2184.9 2115.8,2200.6 2322.5,2200.6 2136.47,2202.06 2157.14,2202.06 2177.81,2202.06 2198.48,2202.06 2219.15,2202.06 2239.82,2202.06 2260.49,2202.06 2281.16,2202.06 2301.83,2202.06 1663.3,2255.84 1683.97,2255.84 1704.64,2255.84 1725.31,2255.84 1745.98,2255.84 1766.65,2255.84 1787.32,2255.84 1807.99,2255.84 1828.66,2255.84 1849.33,2255.84 1870,2255.84 1890.67,2255.84 1911.34,2255.84 1932.01,2255.84 1952.68,2255.84 1973.35,2255.84 1994.02,2255.84 2014.69,2255.84 2035.36,2255.84 2056.03,2255.84 2076.7,2255.84 2097.37,2255.84 2118.04,2255.84 2138.71,2255.84 2159.38,2255.84 2180.05,2255.84 2200.72,2255.84 2221.39,2255.84 2242.06,2255.84 2262.73,2255.84 2283.4,2255.84 2304.07,2255.84 1642.63,2257.3 2324.69,2257.3 1619.7,2273 2340.6,2273 1642.63,2288.7 2324.69,2288.7 1663.3,2290.16 1683.97,2290.16 1704.64,2290.16 1725.31,2290.16 1745.98,2290.16 1766.65,2290.16 1787.32,2290.16 1807.99,2290.16 1828.66,2290.16 1849.33,2290.16 1870,2290.16 1890.67,2290.16 1911.34,2290.16 1932.01,2290.16 1952.68,2290.16 1973.35,2290.16 1994.02,2290.16 2014.69,2290.16 2035.36,2290.16 2056.03,2290.16 2076.7,2290.16 2097.37,2290.16 2118.04,2290.16 2138.71,2290.16 2159.38,2290.16 2180.05,2290.16 2200.72,2290.16 2221.39,2290.16 2242.06,2290.16 2262.73,2290.16 2283.4,2290.16 2304.07,2290.16
  other v3: 2171.27,593.2 2225.49,594 2141.61,623 2197.39,623 2113.2,651.27 2171.27,651.27 2229.34,651.27 2143.17,676.22 2201,680.8 2224.67,706 2114.5,707 2171.27,709.34 436.9,997.1 414.26,1034.5 459.54,1034.5 436.9,1071.9 1511.53,1106.12 1540.78,1106.12 1571.55,1107 1571.55,1134 1541.04,1161.85 1571.55,1161.76
  other v4: 414.9,1000.5 458.9,1000.5 414.9,1062.5 458.9,1062.5 1511.46,1161.43
  other v5: 1827.46,1926.43 1860.46,1926.43 1892.46,1926.43 1923.46,1926.43 1845.46,1970.43 1876.66,1970.48 1907.46,1971.43
  other v7: 2287.53,944.5
  other v8: 2271,1235
MCU_3V3: J6.1 R130.1 | length 2473.3
  TOP w35: v1(713,382.5) 715.2,384.7 1215.7,384.7 1258.5,427.5 v1(1273,427.5)
  L3 w15: v1(1273,427.5) 1273,462 1305,494 1538,494 1882,150 2210,150 2287.3,227.3 2287.3,341.3 v1(2399,453)
  BOTTOM w15: v1(2399,453) 2418,453 2487,522 R130.1@2525.5,522
  BOTTOM w40: J6.1@527.5,298.28 527.5,316.5 593.5,382.5 v1(713,382.5)
MCU_5V: J6.2 R115.1 | length 7.8
  BOTTOM w40: J6.2@527.5,520.72 J6.2@527.5,528.5
MCU_SOP0: R36.1 R93.2 | length 1668.9
  TOP w4: R93.2@1005.82,566.95 1008.14,566.95 1035,593.81 v1(1035,639) ; v1(1386,1934) 1386,1950 1399.73,1963.73 R36.1@1427.25,1963.73
  BOTTOM w4: v1(1035,639) 1179.2,783.2 1179.2,1027.91 1168,1039.11 1168,1090.61 1186.2,1108.81 1188,1110.56 1188,1122.42 1212.2,1146.62 1212.2,1250.91 1223.2,1261.91 1223.2,1313.83 1206,1331.03 1206,1406.7 1212.96,1413.67 1212.96,1440.77 1183,1470.74 1183,1698.72 1287.2,1802.92 1287.2,1889.32 1312.89,1915 1324,1915 1343,1934 v1(1386,1934)
MCU_SOP1: R35.1 R112.2 | length 2023.8
  TOP w4: R112.2@649.32,428.65 682,461.33 682,551 723.2,592.2 866.2,592.2 892,618 v1(927,618) ; v1(1308,1935) 1329,1935 1334,1940 R35.1@1334,1958.01
  BOTTOM w4: v1(927,618) 941,632 999.28,632 1169.2,801.92 1169.2,1023.77 1157.17,1035.8 1157.17,1092.55 1177.2,1112.58 1177.2,1125.76 1202.2,1150.76 1202.2,1255.05 1213.2,1266.05 1213.2,1311.1 1196,1328.3 1196,1410.85 1203.96,1418.81 1203.96,1437.05 1173,1468.01 1173,1703.29 1278.2,1808.5 1278.2,1922.74 1290.46,1935 v1(1308,1935)
MCU_SOP2: R32.1 R101.2 | length 2554.1
  TOP w4: R101.2@366.98,592.54 366.98,655.98 390,679 615,679 674,620 871,620 v1(898,647) ; v1(1246.21,2142.71) 1276,2142.71 R32.1@1277.55,2142.71
  BOTTOM w4: v1(898,647) 1000.14,647 1159.2,806.06 1159.2,1019.63 1147.17,1031.66 1147.17,1096.02 1168.2,1117.05 1168.2,1130.91 1192.2,1154.91 1192.2,1221.4 1167,1246.6 1167,1274.15 1193.2,1300.35 1193.2,1318.38 1185,1326.58 1185,1383.81 1153.2,1415.61 1153.2,1443.66 1153,1443.86 1153,1691.26 1122,1722.26 1122,1852.19 1149.58,1879.77 1192.93,1879.77 1259,1945.85 1259,2019 1310,2070 1310,2105 1272.29,2142.71 v1(1246.21,2142.71)
MISO1: R6.2 R7.2 U14.1 | length 1094.8
  TOP w4: R6.2@1124.05,2227.73 1128.05,2227.73 R7.2@1161.25,2227.73 ; U14.1@1126.62,1297.53 1126.62,1307.62 1134,1315 v1(1146,1315) 1146,1317 v1@1149,1320 ; v1@1152.82,2161.82 1161.25,2170.25 R7.2@1161.25,2227.73 ; R7.2@1161.25,2229.73 R7.2@1161.25,2227.73
  BOTTOM w4: v1(1146,1315) 1123,1338 1123,1583 1026.8,1679.2 1026.8,1808.8 1047.8,1829.8 1047.8,1844.8 1098,1895 1098,2106 v1(1152.82,2160.82)
MOSI1: R4.2 R28.1 U14.4 | length 1619.9
  TOP w4: R28.1@931.5,2142.39 917,2156.89 917,2183 924,2190 v1(968,2190) 968,2218 979.73,2229.73 R4.2@1022.55,2229.73 ; v1(988,1299) 988.58,1299 1009.08,1319.5 1066.5,1319.5 1079.38,1306.62 U14.4@1079.38,1299.5
  BOTTOM w4: v1(968,2190) 968,2137 963,2132 863,2132 857.3,2126.3 857.3,1955.58 809.92,1908.2 807.05,1908.2 795.8,1896.95 795.8,1841.2 809,1828 835,1828 871,1792 894,1792 907,1805 917,1805 928,1794 928,1790 910,1772 910,1765.54 921,1754.54 931.46,1754.54 949.92,1773 961,1773 966,1768 966,1753.08 947.46,1734.54 947.46,1728.08 955.39,1720.15 955.39,1701.17 1081,1575.56 1081,1413 988,1320 v1(988,1299)
NetC1_2: C1.2 C2.2 R37.2 U1.8 | length 168.2
  TOP w15: U1.8@1987.33,2022.18 2014.82,2022.18 2027.4,2009.6 C2.2@2044.9,2009.6
  TOP w20: C2.2@2044.9,2009.6 2045.09,2009.41 2046.4,2008.1 2096.6,2008.1 2097,2008.5 2106,2008.5 2149.5,2008.5
NetC16_2: C16.2 R78.1 U3.3 | length 230.9
  TOP w20: C16.2@988.9,920 988.9,880 R78.1@989.68,880 1025,880 1091.31,946.31 U3.3@1091.31,1006.33 U3.3@1091.31,1007.31
NetC18_1: C18.1 U8.2 | length 324.7
  L4 w10: v1(2465.17,320.28) 2465.17,317.58 2494.36,288.39 2494.36,158.26 v1(2530.31,122.31)
  BOTTOM w10: U8.2@2460.2,121.62 2529.62,121.62 v1(2530.31,122.31) ; v1(2465.17,320.28) 2486.72,320.28 C18.1@2488,319 C18.1@2488,325
NetC18_2: C18.2 L1.1 U8.9
NetC24_2: C24.2 R85.1 R87.2 | length 129.4
  TOP w4: R87.2@1076.7,672.5 1092.6,672.5 1096.5,676.4 1096.5,691.4 1115.5,710.4 1117.1,710.4 1118.7,710.4 1138,691.1 1138,678 1144.1,671.9 R85.1@1158,671.9
NetC32_1: C32.1 R84.2 U8.1
NetC49_2: C49.2 R134.1 U6.68 | length 104.2
  BOTTOM w7: U6.68@814.94,1444.89 871.46,1444.89 875.36,1440.99 R134.1@875.75,1440.6
  BOTTOM w20: C49.2@875.05,1481.9 875.75,1481.2 R134.1@875.75,1440.6
NetC63_1: C63.1 U6.88 Y2.1 | length 188.9
  BOTTOM w4: U6.88@814.94,1129.93 814.94,1129.5 910.23,1129.5 934.17,1105.56 937.99,1105.56 C63.1@977.23,1144.79
NetC66_2: C66.2 C67.2 R140.1 U6.9 U7.1 | length 249.9
  BOTTOM w7: 166.67,1129.93 U6.9@208.64,1129.93
  BOTTOM w15: C66.2@146.88,1130.1 166.5,1130.1 166.67,1129.93
  BOTTOM w20: U7.1@53.36,1214.49 U7.1@55.32,1214.49 63.44,1214.49 78.41,1199.52 R140.1@107.96,1199.52 108.75,1199.52 108.75,1190.38 146.49,1152.64 C66.2@146.88,1130.1 146.88,1089.13 146.74,1088.99 C67.2@146.55,1088.8
NetC70_1: C70.1 U6.89 Y2.3 | length 385.2
  BOTTOM w4: U6.89@814.94,1114.18 856.82,1114.18 891,1080 891,998.19 908.39,980.8 946.8,980.8 969.2,1003.2 999.5,1003.2 C70.1@1019.51,983.19 ; C70.1@1019.7,983 1033.27,996.57 Y2.3@1033.27,1037.28
NetC71_2: C71.2 R154.1 U6.96 | length 174.6
  TOP w20: v1(751,990.5) 763.64,990.5 783.64,1010.5 C71.2@794.31,1010.5 C71.2@794.7,1010.5 ; R154.1@796,955.68 C71.2@796,1008.81
  BOTTOM w7: v1(751,990.5) 764.45,1003.95 U6.96@814.94,1003.95
NetC72_2: C72.2 R122.1 R145.2 U5.3 | length 127.1
  BOTTOM w9: R122.1@1531.62,1266 1531.62,1244.38 1539,1237 C72.2@1539,1232 1541,1230 U5.3@1541.04,1198.96 ; R122.1@1532.62,1273 1555,1273 1564.38,1282.38 R145.2@1585,1282.38
NetC73_1: C73.1 U5.13 | length 65.5
  BOTTOM w10: U5.13@1541,1069.08 1541,1005 C73.1@1542,1004
NetC77_1: C77.1 R150.1 U4.31 | length 157.2
  BOTTOM w10: U4.31@2265.76,602.06 2277.94,602.06 2318,562 C77.1@2358.38,562 2357.7,561.32 R150.1@2357.7,514.32
NetC78_1: C78.1 R157.1 U4.30 | length 901.1
  L3 w10: v1(2308,610) 2308,600.79 2357.7,551.09 2357.7,536.6 2425.42,468.88 2425.42,403.68 v1(2377,355.26)
  L4 w10: v1(2377,355.26) 2476.1,355.26 2492.97,338.39 2704,338.39 2746.71,381.1 2746.71,419.29 v1(2741,425)
  BOTTOM w10: U4.30@2265.76,621.74 2282.26,621.74 2294,610 v1(2308,610) ; R157.1@2686.62,460 C78.1@2741.38,460 2741.38,425.38 v1(2741,425)
NetC79_1: C79.1 F1.1 L7.1
NetC85_1: C85.1 C88.1 P7.2 R61.2 U11.3 U11.4 | length 973.8
  TOP w10: 378.6,925.6 403.8,900.4 C88.1@506.32,900.4 506.7,900.4 506.9,900.6 R61.2@506.9,941.1
  L4 w20: P7.2@171.94,1746.15 171.94,1699.06 251,1620 251,1400 201.6,1350.6 201.6,1185.4 294.9,1092.1 v1(294.9,1043.5)
  other v1: 292.9,1007.5
NetC88_2: C88.2 R61.1 R193.2 U11.5 | length 145
  TOP w4: U11.5@495.96,996.11 544.9,996.11 544.7,995.91 R193.2@544.7,986.7 544.7,901 C88.2@545.3,900.4
NetC91_2: C91.2 R196.1 U12.5 | length 88.8
  TOP w12: U12.5@2001.63,876.9 2040.22,876.9 C91.2@2041,877.69
  TOP w20: C91.2@2041,877.69 2089.63,877.69 R196.1@2090,877.32
NetC92_2: C92.2 R200.1 U13.5 | length 88.8
  TOP w12: R200.1@222.7,935.2 R200.1@223,935.5 ; U13.5@240,976.27 240,952.5 223.09,935.59 R200.1@223,935.5 ; C92.2@263.6,935.5 R200.1@223,935.5
NetD2_1: D2.1@37.49,1105.47 R80.2 | length 67.8
  TOP w10: D2.1@36.3,1106.06 36.89,1105.47 D2.1@37.49,1105.47 D2.1@40.34,1105.47
  TOP w20: R80.2@-27.25,1106.06 D2.1@36.3,1106.06
NetD5_2: D5.2 R118.2 | length 72.7
  TOP w20: D5.2@105,693.72 v1(105,731)
  BOTTOM w20: R118.2@88,759.38 105,742.38 v1(105,731)
NetDS1_1: DS1.1 R90.1 | length 156.3
  TOP w6: 198.59,647.59 216,665 216,722 207,731 R90.1@207,751.32
  TOP w7: DS1.1@157,647.59 198.59,647.59
NetDS2_1: DS2.1 R202.1 | length 58.7
  TOP w20: DS2.1@52,704.54 DS2.1@52,705.53 v1(52,734)
  BOTTOM w20: R202.1@45,760.32 45,741 v1(52,734)
NetDS3_1: DS3.1 R103.1 | length 47.8
  TOP w20: R103.1@-18,599.68 DS3.1@-18,643.52 DS3.1@-18,647.46
NetDS3_2: DS3.2 Q1.3 | length 225.1
  TOP w20: DS3.2@-18,704.54 -15.54,704.54 19,670 19,609 45.97,582.03 Q1.3@120.58,582.03
NetDS4_1: DS4.1 R117.1 | length 54.4
  TOP w10: DS4.1@255.6,439.92 305.16,439.92 R117.1@308.61,436.47
NetDS4_2: DS4.2 Q2.3 | length 161
  TOP w20: v1(212,497) DS4.2@255.6,497
  BOTTOM w20: Q2.3@177.24,394 177.24,462.24 v1(212,497)
NetF1_2: F1.2 P6.1
NetJ1_1: J1.1 J1.2 J1.3 R34.1
NetJ1_4: J1.4 R67.1 | length 169.2
  TOP w4: J1.4@1079.8,1773.27 1079.8,1731.4 1127,1684.2 1127,1627.46 R67.1@1124.25,1624.71
NetJ1_5: J1.5 R29.2 | length 246.5
  TOP w4: R29.2@963.83,2116.73 963.83,2095.17 v1(969,2090) ; J1.5@1060.11,1999.25 1060.11,2039.11 1066.9,2045.9 1066.9,2046.64 1067,2046.74 v1(1067,2092)
  BOTTOM w4: v1(969,2090) 999,2120 1039,2120 v1(1067,2092)
NetJ1_6: J1.6 R66.1 | length 161.7
  TOP w4: J1.6@1060.11,1773.27 1060.11,1731.4 1080,1711.51 1080,1636.46 R66.1@1091.75,1624.71
NetJ1_7: J1.7 R17.2 | length 355.3
  TOP w4: J1.7@1040.43,1999.25 1040.43,2040.43 1053.4,2053.4 1053.4,2074.9 1047.36,2080.93 1047.36,2106.36 1081,2140 v1(1081,2159) ; R17.2@1082,2252.99 R17.2@1082,2255.71 1082,2274 v1(1095,2287)
  BOTTOM w4: v1@1082,2158 1095,2171 v1(1095,2287)
NetJ1_8: J1.8 R65.1 | length 159.6
  TOP w4: J1.8@1040.43,1773.27 1040.43,1732.08 1063.2,1709.31 1063.2,1628.66 R65.1@1059.25,1624.71
NetJ1_9: J1.9 R75.2 | length 1335.3
  TOP w4: J1.9@1020.33,1999.06 1020.33,1958.33 1013,1951 1013,1944 1020,1937 v1(1034,1937) ; v1(1136,1158) 1147,1147 1174,1147 1202,1175 1236.77,1175 1243.76,1168.01 1250,1168.01 R75.2@1251,1168.01
  BOTTOM w4: v1(1034,1937) 1032.71,1937 1024.26,1928.55 1024.26,1911.21 1020.06,1907 1004,1907 1000,1903 1000,1887 1004,1883 1022,1883 1027,1878 1027,1839.85 1000.3,1813.15 1000.3,1672.56 1093,1579.86 1093,1407 1041.5,1355.5 1041.5,1348.5 1056,1334 1056,1322 1051,1317 1041,1317 1026,1332 1018,1332 1013.7,1327.7 1013.7,1311.67 1008,1305.97 1008,1287 1020,1275 1036.59,1275 1045.59,1266 1050.68,1260.91 1057.47,1260.91 1061.02,1264.46 1067.81,1264.46 1077.99,1254.28 1077.99,1247.49 1071.05,1240.54 1057.79,1227.29 1057.79,1220.5 1067.98,1210.32 1074.76,1210.32 1088.02,1223.57 1093.94,1229.5 1100.73,1229.5 1110.91,1219.32 1110.91,1212.53 ; 1108.69,1210.31 1110.91,1212.53 ; v1(1136,1158) 1136.6,1158.6 1136.6,1182.72 1132.71,1186.61 1116.18,1186.61 1107.39,1195.41 1107.39,1204.21 1107.39,1209 1110.91,1212.53
NetJ1_10: J1.10 R64.1 | length 151
  TOP w4: J1.10@1020.74,1773.27 1020.74,1630.58 R64.1@1026.61,1624.71
NetJ1_11: J1.11 R28.2 | length 163.5
  TOP w4: R28.2@931.5,2116.41 931.5,2097.5 956.2,2072.8 986.2,2072.8 1001.06,2057.94 J1.11@1001.06,1999.25
NetJ1_12: J1.12 R7.1 | length 675.6
  TOP w4: J1.12@1001.06,1773.27 1001.06,1773.46 1001.06,1815.06 1026,1840 v1(1075,1840) ; R7.1@1161.25,2255.71 1161.25,2292.25 v1(1166,2297)
  BOTTOM w4: v1(1075,1840) 1092,1857 1092,1869 1156,1933 1156,2052.85 1180,2076.85 1180,2283 v1(1166,2297)
NetJ1_13: J1.13 R27.2 | length 167
  TOP w10: 971,2058 981.37,2047.63 J1.13@981.37,1999.25
  TOP w15: R27.2@898.8,2116.51 898.8,2103.7 944.5,2058 971,2058
NetJ1_14: J1.14 R63.1 | length 172
  TOP w4: R63.1@962.11,1624.71 1000,1662.6 1000,1713.39 981.37,1732.02 J1.14@981.37,1773.27
NetJ1_15: J1.15 R54.2 | length 142.8
  TOP w4: J1.15@961.69,1999.25 961.69,1999.06 961.69,1945.31 978.71,1928.29 v1(996.42,1928.29)
  BOTTOM w4: R54.2@984,1886.99 984,1917 995.29,1928.29 v1(996.42,1928.29)
NetJ1_16: J1.16 R62.1 | length 161.7
  TOP w4: R62.1@929.85,1624.71 929.85,1677.85 961.69,1709.69 J1.16@961.69,1773.27
NetJ1_17: J1.17 R55.2 | length 122.8
  TOP w4: J1.17@942,1999.25 942,1999.06 942,1938 v1(959,1921)
  BOTTOM w4: R55.2@951,1886.79 951,1913 v1(959,1921)
NetJ1_19: J1.19 R56.2 | length 114.5
  TOP w4: v1(919,1920) 922.32,1923.32 922.32,1999.06 J1.19@922.32,1999.25
  BOTTOM w4: R56.2@918.5,1886.29 918.5,1919.5 v1(919,1920)
NetJ1_21: J1.21 R57.2 | length 145
  TOP w4: v1(866,1914) 866,1916 902.63,1952.63 902.63,1999.06 J1.21@902.63,1999.25
  BOTTOM w4: v1(866,1914) 877.5,1914 878.5,1915 885.6,1907.9 R57.2@885.6,1886.29
NetJ1_23: J1.23 R179.2 | length 148.1
  TOP w4: R179.2@811,2117.51 882.95,2045.56 J1.23@882.95,1999.25
NetJ1_25: J1.25 R180.2 | length 165
  TOP w4: R180.2@777.7,2117.71 777.7,2115.3 R180.2@778,2115.01 804,2089 823,2089 863.26,2048.74 J1.25@863.26,1999.25
NetJ1_26: J1.26 R59.1 | length 167.6
  TOP w5.2: R59.1@833.05,1624.71 825.2,1632.56 825.2,1665.7 858.52,1699.02 858.52,1717.31 863.26,1722.05 J1.26@863.26,1773.27
NetJ1_27: J1.27 R181.2 | length 276.9
  TOP w4: R181.2@753.5,2221.31 753.5,2203.5 762.73,2194.27 762.73,2099.27 767,2095 786.69,2095 805.69,2076 816,2076 843.58,2048.42 J1.27@843.58,1999.25
NetJ1_28: J1.28 R58.1 | length 176.8
  TOP w5.2: R58.1@800.55,1624.71 811.71,1624.71 815,1628 815,1669.92 822.85,1677.77 ; 822.85,1677.78 848.32,1703.25 848.32,1717.31 843.58,1722.05 J1.28@843.58,1773.27
NetJ1_29: J1.29 R182.2 | length 163
  TOP w4: R182.2@745,2112.01 R182.2@745,2109.01 745,2094 753,2086 783,2086 823.89,2045.11 J1.29@823.89,1999.25
NetJ1_31: J1.31 R183.2 | length 279.2
  TOP w4: R183.2@721,2221.71 721,2195 727.8,2188.2 727.8,2087.2 741,2074 779,2074 804.21,2048.79 J1.31@804.21,1999.25
NetJ1_33: J1.33 R184.2 | length 168.3
  TOP w4: R184.2@712,2117.01 712,2085 734,2063 769,2063 784.52,2047.48 J1.33@784.52,1999.25
NetJ1_44: J1.44 R53.1 | length 168.4
  TOP w5.2: R53.1@638.25,1624.71 638.25,1662.24 680.5,1704.49 680.5,1718.99 686.1,1724.59 J1.44@686.1,1773.27
NetJ1_46: J1.46 R52.1 | length 176.9
  TOP w5.2: R52.1@605.75,1624.71 628.05,1647.01 628.05,1666.47 670.3,1708.72 670.3,1719.2 666.41,1723.09 J1.46@666.41,1773.27
NetJ1_50: J1.50 R51.1 | length 177.5
  TOP w5.2: R51.1@573.25,1624.71 565.2,1632.76 565.2,1644.71 622,1701.51 622,1720.51 627.04,1725.55 J1.50@627.04,1773.27
NetJ1_51: J1.51 R23.2 | length 127.7
  TOP w4: R23.2@582.61,2116.73 590,2109.34 590,2058 607.36,2040.64 J1.51@607.36,1999.25
NetJ1_52: J1.52 R50.1 | length 187.2
  TOP w5.2: R50.1@540.75,1624.71 553.36,1624.71 556,1627.35 556,1649.94 611.8,1705.74 611.8,1719.71 607.36,1724.15 J1.52@607.36,1773.27
NetJ1_53: J1.53 R22.2 | length 137.5
  TOP w4: R22.2@550.11,2116.73 544.7,2111.32 544.7,2083.31 587.67,2040.34 J1.53@587.67,1999.25
NetJ1_55: J1.55 R33.2 | length 138
  TOP w4: R33.2@517.39,2116.29 535,2098.68 535,2073 567.99,2040.01 J1.55@567.99,1999.25
NetJ1_56: J1.56 R49.1 | length 182.6
  TOP w5.2: R49.1@508.25,1624.71 497.03,1635.93 497.03,1642.53 563.2,1708.7 563.2,1717.88 567.99,1722.67 J1.56@567.99,1773.27
NetJ1_57: J1.57 R21.2 | length 164.6
  TOP w4: R21.2@484.35,2116.73 480,2112.38 480,2080.01 495.01,2065 524,2065 548.3,2040.7 J1.57@548.3,1999.25
NetJ1_58: J1.58 R48.1 | length 182.6
  TOP w5.2: R48.1@475.61,1624.71 486.83,1635.93 486.83,1646.76 553,1712.93 553,1717.35 548.3,1722.05 J1.58@548.3,1773.27
NetJ1_59: J1.59 R20.2 | length 165.6
  TOP w4: R20.2@452.11,2116.73 452.11,2087.89 485,2055 513.01,2055 528.62,2039.39 J1.59@528.62,1999.25
NetJ2_1: J2.1 R111.2 | length 58.2
  TOP w15: R111.2@2155.99,369 2155.99,340.01 2156,315.04 J2.1@2159,312.04
NetJ3_1: J3.1 R85.2 U3.7 | length 1034
  TOP w7: v1(1111,585) 1179.1,653.1 1179.1,693.8 1163.2,709.7 1158,709.7 1157,709.7 1141.31,725.39 U3.7@1141.31,798.65
  BOTTOM w7: J3.1@808.4,-25.28 865.72,-25.28 1079,188 1079,435 1097.7,453.7 1097.7,501.68 1094,505.38 1094,569 1110,585 v1(1111,585)
NetJ3_3: J3.3 R87.1 U3.6 | length 1242
  TOP w7: v1(1068,513) 1054,527 1054,690 1075.89,711.89 1091.31,727.31 U3.6@1091.31,798.65
  BOTTOM w7: J3.3@532.8,-25.28 593.08,35 868,35 1062,229 1062,435.71 1085,458.71 1085,496 v1(1068,513)
NetJ5_1: J5.1 R19.2 | length 203
  TOP w4: v1(412,2079) 412,2095 419.25,2102.25 R19.2@419.25,2116.73
  BOTTOM w4: v1(412,2079) 469.5,2079 527.5,2021 J5.1@527.5,1998.28
NetJ5_3: J5.3 R24.2 | length 112.9
  BOTTOM w4: J5.3@627.5,1998.28 628.11,1997.67 R24.2@628.11,1885.6
NetJ5_5: J5.5 R25.2 | length 120.8
  BOTTOM w4: J5.5@727.5,1998.28 742.81,1982.97 R25.2@742.81,1883.8
NetJ5_6: J5.6 R1.1 | length 449.8
  BOTTOM w4: J5.6@727.5,2220.72 727.5,2244.5 770.5,2287.5 823.1,2287.5 902.5,2366.9 1076,2366.9 1082.91,2359.99 R1.1@1100,2359.99
NetJ5_8: J5.8 R9.1 | length 102
  TOP w4: v1(791.2,2256.2) 792.69,2254.71 R9.1@829.75,2254.71
  BOTTOM w4: v1(791.2,2256.2) 812.2,2256.2 827.5,2240.9 J5.8@827.5,2220.72
NetJ5_9: J5.9 R26.2 | length 152.1
  TOP w4: R26.2@866.7,2116.61 866.7,2096.7 v1(887.4,2076)
  BOTTOM w4: v1(887.4,2076) 902,2076 927.5,2050.5 J5.9@927.5,1998.28
NetJ5_10: J5.10 R2.1 | length 201.2
  TOP w4: v1(902.66,2328) 930.05,2300.61 R2.1@930.05,2255.71
  BOTTOM w4: v1(902.66,2328) 927.5,2303.16 J5.10@927.5,2220.72
NetJ5_11: J5.11 R18.2 | length 124
  TOP w4: R18.2@1028.21,2117.08 1028.21,2096.79 1034.1,2090.9 v1(1034.1,2061)
  BOTTOM w4: J5.11@1027.5,1998.28 1034.1,2004.88 v1(1034.1,2061)
NetJ5_12: J5.12 R4.1 | length 118
  TOP w4: R4.1@1022.55,2255.71 1022.55,2273.55 v1(1040,2291)
  BOTTOM w4: J5.12@1027.5,2220.72 1027.5,2278.5 v1(1040,2291)
NetJ5_13: J5.13 R31.2 | length 145.3
  TOP w4: v1(1155,2079) 1166,2079 1176.75,2089.75 R31.2@1176.75,2116.73
  BOTTOM w4: J5.13@1127.5,1998.28 1127.5,2040.5 1155,2068 v1(1155,2079)
NetJ5_14: J5.14 R6.1 | length 401.4
  TOP w4: v1(1122,2307) 1144,2285 1144,2271.66 R6.1@1128.05,2255.71
  BOTTOM w4: v1(1122,2307) 1122,2338 1144,2360 1209,2360 1215,2354 1215,2325 1207,2317 1157,2317 1127.5,2287.5 J5.14@1127.5,2220.72
NetJ5_15: J5.15 R32.2 | length 141.2
  TOP w4: R32.2@1277.55,2116.73 1278,2116.28 1278,2116.01 1278,2084 v1(1280,2082)
  BOTTOM w4: J5.15@1227.5,1998.28 1227.5,2021.5 1280,2074 v1(1280,2082)
NetJ5_16: J5.16 R10.1 | length 134
  TOP w4: R10.1@1239.25,2254.71 1239.25,2284.25 v1(1252,2297)
  BOTTOM w4: J5.16@1227.5,2220.72 1227.5,2272.5 v1(1252,2297)
NetJ5_17: J5.17 R35.2 | length 137.7
  TOP w4: R35.2@1334,1983.99 1334,1995 1337.5,1998.5 1355.59,1998.5 v1(1382.33,1971.76)
  BOTTOM w4: J5.17@1327.5,1998.28 1355.81,1998.28 v1(1382.33,1971.76)
NetJ5_18: J5.18 R8.1 | length 92.8
  BOTTOM w4: J5.18@1327.5,2220.72 1327.5,2284.51 R8.1@1348,2305.01
NetJ5_19: J5.19 R36.2 | length 91.5
  TOP w4: R36.2@1427.25,1989.71 1441.54,2004 v1(1469,2004)
  BOTTOM w4: J5.19@1427.5,1998.28 1433.22,2004 v1(1469,2004)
